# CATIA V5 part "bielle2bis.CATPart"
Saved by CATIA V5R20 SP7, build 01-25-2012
Part number: bielle2
Bounding box of the stored display mesh (mm): x 0 to 30, y -90 to 117.223, z -10 to 40.291
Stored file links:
  J:\IAO_Mecanisme_991\IAO_Mecanisme_991_CATIA\Assemblage\bielle2ter.CATPart
  J:\IAO_Mecanisme_991\IAO_Mecanisme_991_CATIA\Assemblage\Ass_IAO_991_skl.CATProduct
  J:\IAO_Mecanisme_991\IAO_Mecanisme_991_CATIA\skl_bielle_2.CATPart
  J:\IAO_Mecanisme_991\IAO_Mecanisme_991_CATIA\skl_rainure_circulaire.CATPart
  J:\IAO_Mecanisme_991\IAO_Mecanisme_991_CATIA\Assemblage\bati.CATPart
  J:\IAO_Mecanisme_991\IAO_Mecanisme_991_CATIA\Assemblage\rainure_circulaire.CATPart
  J:\IAO_Mecanisme_991\IAO_Mecanisme_991_CATIA\skl_bati.CATPart
  J:\IAO_Mecanisme_991\IAO_Mecanisme_991_CATIA\Assemblage\excentrique.CATPart
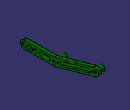
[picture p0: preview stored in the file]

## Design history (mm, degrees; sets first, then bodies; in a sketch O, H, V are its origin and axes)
Set1
  Plane1 "plan_ref_yz": linked copy from another document
  DatumSurface1: linked copy from another document
  Line1: linked copy from another document
  Line2: linked copy from another document
  DatumPoint1: linked copy from another document
  Point1: linked copy from another document
  Line3: linked copy from another document
  DatumPoint2: linked copy from another document
  DatumPoint3: linked copy from another document
  DatumSurface2: linked copy from another document
  DatumCurve1: linked copy from another document
  DatumCurve2: linked copy from another document
Body1 (main body)
  Plane2: type Offset, RefPlane DatumSurface1, Offset 2, reversed
  Sketch1 on Plane2, origin (22, 0, 0), H (0, -1, 0), V (0, 0, 1)
    arc A1 centre (80, 0) radius 10 from (80, -10) to (80.049, 9.9999) ccw
    point P3 (80, 0)
    reference projected point E1 (80, 0) from vertex of DatumPoint1
    line L1 (80, -10) -> (-1.3864, -10)
    point P5 (-1.3864, -10)
    line L2 (-1.3864, -10) -> (-109.9748, 20.6992)
    point P6 (-1.3864, -10)
    point P7 (-109.9748, 20.6992)
    arc A2 centre (-107.2543, 30.322) radius 10 from (-104.5338, 39.9449) to (-109.9748, 20.6992) ccw
    point P8 (-107.2543, 30.322)
    point P9 (-109.9748, 20.6992)
    reference projected point E2 (-107.2543, 30.322) from Point1
    line L3 (80.049, 9.9999) -> (0, 10.3919)
    point P10 (0, 10.3919)
    line L4 (0, 10.3919) -> (-104.5338, 39.9449)
    point P11 (0, 10.3919)
    reference projected line E3 (-107.2543, 30.322) -> (0, 0) from Line1
    reference projected line E4 (-107.2543, 30.322) -> (0, 0) from Line1
    circle A3 centre (80, 0) radius 5
    point P12 (80, 0)
    reference projected point E5 (80, 0) from DatumPoint1
    point P13 (0, 0)
    circle A4 centre (0, 0) radius 5
    reference projected point E6 (0, 0) from vertex of DatumPoint2
    point P14 (-107.2543, 30.322)
    circle A5 centre (-107.2543, 30.322) radius 5
    circle A6 centre (50, 0) radius 5
    point P15 (50, 0)
    reference projected point E7 (50, 0) from vertex of DatumPoint3
    radius A2 = 10
    radius A1 = 10
    radius A4 = 5
    radius A3 = 5
    radius A5 = 5
    radius A6 = 5
    coincidence: P3 E1, P9 L2, P9 P7, P8 E2, P10 V, P11 L3, P11 P10, P6 P5, E5 P12, E6 P13, P8 P14, E7 P15
    tangency: L1 A1, L2 A2, L3 A1, L4 A2
    horizontal: L1 H
    parallelism: L4 E3
    symmetry: L2 L4 E4
  Pad1: profile Sketch1, direction (1, 0, 0), length 8
  Sketch2 on start face of Pad1, origin (22, 0, 0), H (0, -1, 0), V (0, 0, 1)
    circle A1 centre (-107.2543, 30.322) radius 5
    point P1 (-107.2543, 30.322)
    reference projected point E1 (-107.2543, 30.322) from Point1
    reference projected circle E2 centre (-107.2543, 30.322) radius 5 from edge [start face of Pad1 | face of Pad1 from Sketch1.A5]
    coincidence: P1 E1, A1 E2
  Pad2: profile Sketch2, direction (-1, 0, 0), length 12, opposite side length 5
  Sketch3 on start face of Pad1, origin (22, 0, 0), H (0, -1, 0), V (0, 0, 1)
    circle A1 centre (0, 0) radius 5
    reference projected circle E1 centre (0, 0) radius 5 from edge [start face of Pad1 | face of Pad1 from Sketch1.A4]
    coincidence: A1 E1
  Pad3: profile Sketch3, direction (-1, 0, 0), up to DatumSurface2, opposite side length 5
  Sketch4 on end face of Pad2, origin (10, 0, 0), H (0, -1, 0), V (0, 0, 1)
    circle A1 centre (-107.2543, 30.322) radius 7.7913
    point P1 (-107.2543, 30.322)
    reference projected point E1 (-107.2543, 30.322) from Point1
    reference projected curve E2 from edge of DatumCurve2
    distance A1 E2 = 0
    coincidence: P1 E1
  Pad4: profile Sketch4, direction (1, 0, 0), length 10
  Plane3: type Offset, RefPlane DatumSurface1, Offset 0
  Sketch5 on end face of Pad1, origin (30, 0, 0), H (0, 1, 0), V (0, 0, 1)
    line L1 (13.074, 8.8921) -> (91.4598, 31.0527)
    point P2 (91.4598, 31.0527)
    line L2 (15.7945, -0.7307) -> (94.1803, 21.4299)
    point P3 (15.7945, -0.7307)
    point P4 (94.1803, 21.4299)
    construction line L3 (109.3224, 30.9067) -> (-43.1077, -12.1871)
    reference projected line E1 (0, 10.3919) -> (104.5338, 39.9449) from edge [end face of Pad1 | face of Pad1 from Sketch1.L4]
    reference projected line E2 (109.9748, 20.6992) -> (1.3864, -10) from edge [end face of Pad1 | face of Pad1 from Sketch1.L2]
    arc A1 centre (92.82, 26.2413) radius 5 from (94.1803, 21.4299) to (91.4598, 31.0527) ccw
    point P7 (92.82, 26.2413)
    point P8 (91.4598, 31.0527)
    arc A2 centre (14.4343, 4.0807) radius 5 from (13.074, 8.8921) to (15.7945, -0.7307) ccw
    point P9 (14.4343, 4.0807)
    point P10 (15.7945, -0.7307)
    reference projected circle E3 centre (107.2543, 30.322) radius 5 from edge [face of Pad1 from Sketch1.A5 | end face of Pad1]
    reference projected circle E4 centre (0, 0) radius 5 from edge [face of Pad1 from Sketch1.A4 | end face of Pad1]
    construction line L4 (-35.0004, 0.1102) -> (-14.9992, 0.1592)
    point P11 (-35.0004, 0.1102)
    point P12 (-14.9992, 0.1592)
    line L5 (-35.0126, 5.1102) -> (-15.0114, 5.1592)
    line L6 (-14.9869, -4.8408) -> (-34.9882, -4.8898)
    arc A3 centre (-14.9992, 0.1592) radius 5 from (-15.0114, 5.1592) to (-14.9869, -4.8408) cw
    arc A4 centre (-35.0004, 0.1102) radius 5 from (-34.9882, -4.8898) to (-35.0126, 5.1102) cw
    reference projected circle E5 centre (0, 0) radius 5 from edge [face of Pad1 from Sketch1.A4 | end face of Pad1]
    reference projected circle E6 centre (-50, 0) radius 5 from edge [face of Pad1 from Sketch1.A6 | end face of Pad1]
    axis line L7 (-41.1937, 0.095) -> (20.8142, 0.2469)
    reference projected line E7 (-80.049, 9.9999) -> (0, 10.3919) from edge [end face of Pad1 | face of Pad1 from Sketch1.L3]
    reference projected line E8 (1.3864, -10) -> (-80, -10) from edge [end face of Pad1 | face of Pad1 from Sketch1.L1]
    construction line L8 (-68, 0) -> (-61.9998, -0.0669)
    point P19 (-68, 0)
    line L9 (-67.9442, 4.9997) -> (-61.944, 4.9328)
    line L10 (-62.0556, -5.0666) -> (-68.0558, -4.9997)
    arc A5 centre (-61.9998, -0.0669) radius 5 from (-61.944, 4.9328) to (-62.0556, -5.0666) cw
    arc A6 centre (-68, 0) radius 5 from (-68.0558, -4.9997) to (-67.9442, 4.9997) cw
    reference projected circle E9 centre (-50, 0) radius 5 from edge [face of Pad1 from Sketch1.A6 | end face of Pad1]
    reference projected circle E10 centre (-80, 0) radius 5 from edge [face of Pad1 from Sketch1.A3 | end face of Pad1]
    distance L1 L2 = 10
    distance P7 E3 = 10
    distance E4 P9 = 10
    distance L5 L6 = 10
    distance P12 E5 = 10
    distance P11 E6 = 10
    distance L9 L10 = 10
    distance A5 E9 = 2
    distance A6 E10 = 2
    symmetry: E1 E2 L3, L1 L2 L3, E7 E8 L7
    coincidence: P7 L3, P8 L1, A1 P4, P2 P8, P9 L3, P10 L2, P10 P3, L4 L7, P19 H
    tangency: A1 L1, A2 L1, A3 L5, A4 L5, A3 L6, A4 L6, L8 A2, A5 L9, A6 L9, A5 L10, A6 L10
  Pocket1: profile Sketch5, direction (-1, 0, 0), length 10
  Sketch6 on start face of Pad1, origin (22, 0, 0), H (0, -1, 0), V (0, 0, 1)
    construction line L1 (-92.82, 26.2413) -> (-14.4343, 4.0807)
    line L2 (-91.4598, 31.0527) -> (-13.074, 8.8921)
    line L3 (-15.7945, -0.7307) -> (-94.1803, 21.4299)
    arc A1 centre (-14.4343, 4.0807) radius 5 from (-13.074, 8.8921) to (-15.7945, -0.7307) cw
    arc A2 centre (-92.82, 26.2413) radius 5 from (-94.1803, 21.4299) to (-91.4598, 31.0527) cw
    reference projected line E1 (-13.074, 8.8921) -> (-91.4598, 31.0527) from edge [start face of Pad1 | face of Pocket1 from Sketch5.L1]
    reference projected arc E2 centre (-14.4343, 4.0807) radius 5 from (-15.7945, -0.7307) to (-13.074, 8.8921) ccw from edge [start face of Pad1 | face of Pocket1 from Sketch5.A2]
    reference projected line E3 (-15.7945, -0.7307) -> (-94.1803, 21.4299) from edge [face of Pocket1 from Sketch5.L2 | start face of Pad1]
    reference projected arc E4 centre (-92.82, 26.2413) radius 5 from (-91.4598, 31.0527) to (-94.1803, 21.4299) ccw from edge [start face of Pad1 | face of Pocket1 from Sketch5.A1]
    tangency: A1 L2, A2 L2, A1 L3, A2 L3
    coincidence: L2 E1, A1 E2, L3 E3, A2 E4
  Pad5: profile Sketch6, direction (1, 0, 0), length 3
